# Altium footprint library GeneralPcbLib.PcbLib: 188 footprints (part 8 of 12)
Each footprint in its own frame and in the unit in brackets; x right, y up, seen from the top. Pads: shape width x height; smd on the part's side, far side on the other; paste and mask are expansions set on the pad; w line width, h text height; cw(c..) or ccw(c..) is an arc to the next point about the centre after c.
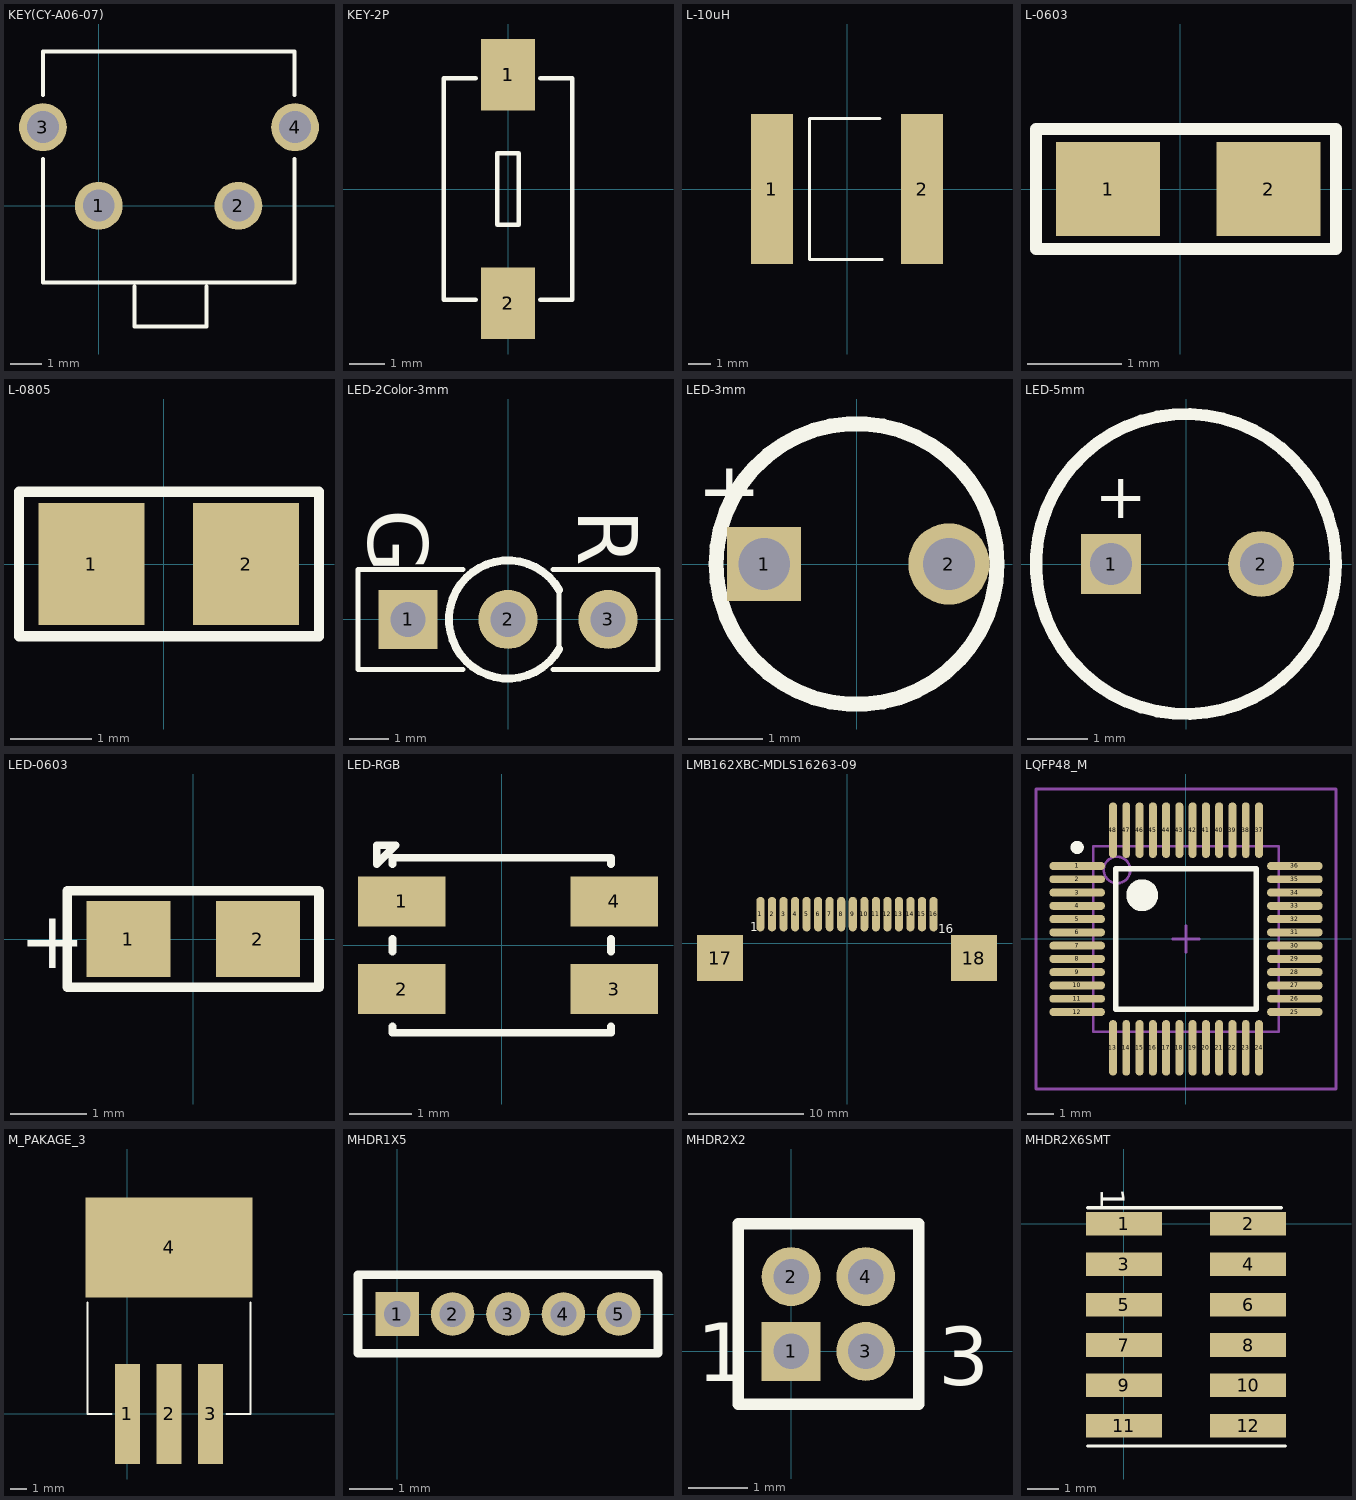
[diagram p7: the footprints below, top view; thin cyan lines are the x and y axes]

## KEY(CY-A06-07) [mil] "肩咪用按键"
pads (4):
  round 60 hole 40: 1(0,0) 2(175,0) 3(-70,98.43) 4(246,98.43)
Top Overlay:
  lines w5: -70,58.43 -70,-96.46 245,-96.46 245,58.43 ; -70,138.43 -70,193.43 0,193.43 245,193.43 245,138.43 ; 45,-101.57 45,-151.57 90,-151.57 135,-151.57 135,-101.57

## KEY-2P [mm]
pads (4):
  rect 1.5x2 smd: 1(0,3.2) 1(0,3.2) 2(0,-3.2) 2(0,-3.2)
Top Overlay:
  lines w0.127: -0.9,-3.1 -1.8,-3.1 -1.8,3.1 -0.9,3.1 ; 0.9,-3.1 1.8,-3.1 1.8,3.1 0.9,3.1 ; -0.3,-1 0.3,-1 0.3,1 -0.3,1 -0.3,-1

## L-10uH [mm] "10uH"
height 3
pads (2):
  rect 1.9x6.8 smd: 1(-3.4,0) 2(3.4,0)
Top Overlay:
  lines w0.127: 1.5,3.2 -1.7,3.2 -1.7,-3.2 1.6,-3.2

## L-0603 [mm]
pads (2):
  rect 1.1x1 smd: 1(-0.762,0) 2(0.938,0)
Top Overlay:
  lines w0.127: -1.524,-0.635 1.651,-0.635 1.651,0.635 -1.524,0.635 -1.524,-0.635

## L-0805 [mm]
pads (2):
  rect 1.3x1.5 smd: 1(-0.889,0) 2(1.011,0)
Top Overlay:
  lines w0.127: -1.778,-0.889 1.905,-0.889 1.905,0.889 -1.778,0.889 -1.778,-0.889

## LED-2Color-3mm [mm]
pads (3):
  rect 1.5x1.5 hole 0.9: 1(-2.54,0)
  round 1.5 hole 0.9: 2(0,0) 3(2.54,0)
Top Overlay:
  lines w0.127: -1.143,-1.27 -3.81,-1.27 -3.81,1.27 -1.143,1.27 ; 1.143,-1.27 3.81,-1.27 3.81,1.27 1.143,1.27 ; 1.299,-0.75 1.299,0.75
  lines w0.203: 1.299,-0.75 cw(c0,0) 1.299,0.75
  text "G" at -3.556,2.794 h1.52
  text "R" at 1.778,2.794 h1.52

## LED-3mm [mm] "100mil"
pads (2):
  rect 1x1 hole 0.7: 1(-1.25,0)
  round 1.1 hole 0.7: 2(1.25,0)
Top Overlay:
  circle w0.203: c0,0 r1.9
  text "+" at -2.159,0.635 h0.76

## LED-5mm [mm]
pads (2):
  rect 1x1 hole 0.7: 1(-1.25,0)
  round 1.1 hole 0.7: 2(1.25,0)
Top Overlay:
  circle w0.203: c0,0 r2.5
  text "+" at -1.524,0.762 h0.76

## LED-0603 [mm]
pads (2):
  rect 1.1x1 smd: 1(-0.85,0) 2(0.85,0)
Top Overlay:
  lines w0.127: -1.651,-0.635 -1.651,0.635 1.651,0.635 1.651,-0.635 -1.651,-0.635
  text "+" at -2.286,-0.381 h0.76

## LED-RGB [mm]
pads (4):
  rect 1.4x0.8 smd: 1(-1.6,0.7) 2(-1.6,-0.7) 3(1.8,-0.7) 4(1.8,0.7)
Top Overlay:
  lines w0.127: -1.75,-1.3 -1.75,-1.4 1.75,-1.4 1.75,-1.3 ; -1.75,-0.1 -1.75,0.1 ; -1.75,1.3 -1.75,1.4 1.75,1.4 1.75,1.3 ; 1.75,-0.1 1.75,0.1 ; -2,1.3 -2,1.6 -1.7,1.6 -2,1.3

## LMB162XBC-MDLS16263-09 [mm] "液晶模块LMB162XBC或者MDLS16263-09"
pads (18):
  oval 0.7x3 smd: 1(-7.5,2.54) 2(-6.5,2.54) 3(-5.5,2.54) 4(-4.5,2.54) 5(-3.5,2.54) 6(-2.5,2.54) 7(-1.5,2.54) 8(-0.5,2.54) 9(0.5,2.54) 10(1.5,2.54) 11(2.5,2.54) 12(3.5,2.54) 13(4.5,2.54) 14(5.5,2.54) 15(6.5,2.54) 16(7.5,2.54)
  rect 4x4 smd: 17(-11,-1.27) 18(11,-1.27)
Top Overlay:
  text "1" at -8.4,1.04 h0.76
  text "16" at 7.928,0.902 h0.76

## LQFP48_M [mm] "Thin QFP, 48-Leads, Body 7x7mm, Pitch 0.5mm, IPC Low Density"
height 1.6
pads (48):
  oval 2.1x0.3 smd: 1(-4.1,2.75) 2(-4.1,2.25) 3(-4.1,1.75) 4(-4.1,1.25) 5(-4.1,0.75) 6(-4.1,0.25) 7(-4.1,-0.25) 8(-4.1,-0.75) 9(-4.1,-1.25) 10(-4.1,-1.75) 11(-4.1,-2.25) 12(-4.1,-2.75) 25(4.1,-2.75) 26(4.1,-2.25) 27(4.1,-1.75) 28(4.1,-1.25) 29(4.1,-0.75) 30(4.1,-0.25) 31(4.1,0.25) 32(4.1,0.75) 33(4.1,1.25) 34(4.1,1.75) 35(4.1,2.25) 36(4.1,2.75)
  oval 0.3x2.1 smd: 13(-2.75,-4.1) 14(-2.25,-4.1) 15(-1.75,-4.1) 16(-1.25,-4.1) 17(-0.75,-4.1) 18(-0.25,-4.1) 19(0.25,-4.1) 20(0.75,-4.1) 21(1.25,-4.1) 22(1.75,-4.1) 23(2.25,-4.1) 24(2.75,-4.1) 37(2.75,4.1) 38(2.25,4.1) 39(1.75,4.1) 40(1.25,4.1) 41(0.75,4.1) 42(0.25,4.1) 43(-0.25,4.1) 44(-0.75,4.1) 45(-1.25,4.1) 46(-1.75,4.1) 47(-2.25,4.1) 48(-2.75,4.1)
Top Overlay:
  circle w0.6: c-1.65,1.65 r0.3
  circle w0.25: c-4.1,3.45 r0.125
  lines w0.2: -2.65,-2.65 2.65,-2.65 2.65,2.65 -2.65,2.65 -2.65,-2.65
Mechanical 13:
  circle w0.1: c-2.6,2.6 r0.5
  lines w0.1: -3.5,-3.5 3.5,-3.5 3.5,3.5 -3.5,3.5 -3.5,-3.5
Mechanical 15:
  lines w0.1: -0.5,0 0.5,0 ; 0,-0.5 0,0.5 ; -5.65,-5.65 5.65,-5.65 5.65,5.65 -5.65,5.65 -5.65,-5.65
3D body: height 1.6, standoff 0, extent -3.5,-3.5 3.5,3.5

## M_PAKAGE_3 [mm]
pads (4):
  rect 1.5x6 smd: 1(0,0) 2(2.5,0) 3(5,0)
  rect 10x6 smd: 4(2.5,10)
Top Overlay:
  lines w0.127: -2.4,6.7 -2.4,0 -0.95,0 ; 5.95,0 7.4,0 7.4,6.7

## MHDR1X5 [mm] "Connector; Header; 5 Position"
pads (5):
  rect 1x1 hole 0.6: 1(0,0)
  round 1 hole 0.6: 2(1.27,0) 3(2.54,0) 4(3.81,0) 5(5.08,0)
Top Overlay:
  lines w0.2: -0.9,-0.9 5.98,-0.9 5.98,0.9 -0.9,0.9 -0.9,-0.9

## MHDR2X2 [mm] "Connector; Header; 2x2 Position"
pads (4):
  rect 1x1 hole 0.6: 1(0,0)
  round 1 hole 0.6: 2(0,1.27) 3(1.27,0) 4(1.27,1.27)
Top Overlay:
  lines w0.2: -0.9,-0.9 2.17,-0.9 2.17,2.17 -0.9,2.17 -0.9,-0.9
  text "3" at 2.5,-0.578 h1
  text "1" at -1.6,-0.508 h1

## MHDR2X6SMT [mm]
height 5.6
pads (12):
  rect 2.4x0.74 smd: 1(0,0) 2(3.9,0) 3(0,-1.27) 4(3.9,-1.27) 5(0,-2.54) 6(3.9,-2.54) 7(0,-3.81) 8(3.9,-3.81) 9(0,-5.08) 10(3.9,-5.08) 11(0,-6.35) 12(3.9,-6.35)
Top Overlay:
  lines w0.102: -1.143,-6.985 5.08,-6.985 ; -1.143,0.508 4.953,0.508
  text "1" at -0.737,1.118 h0.76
